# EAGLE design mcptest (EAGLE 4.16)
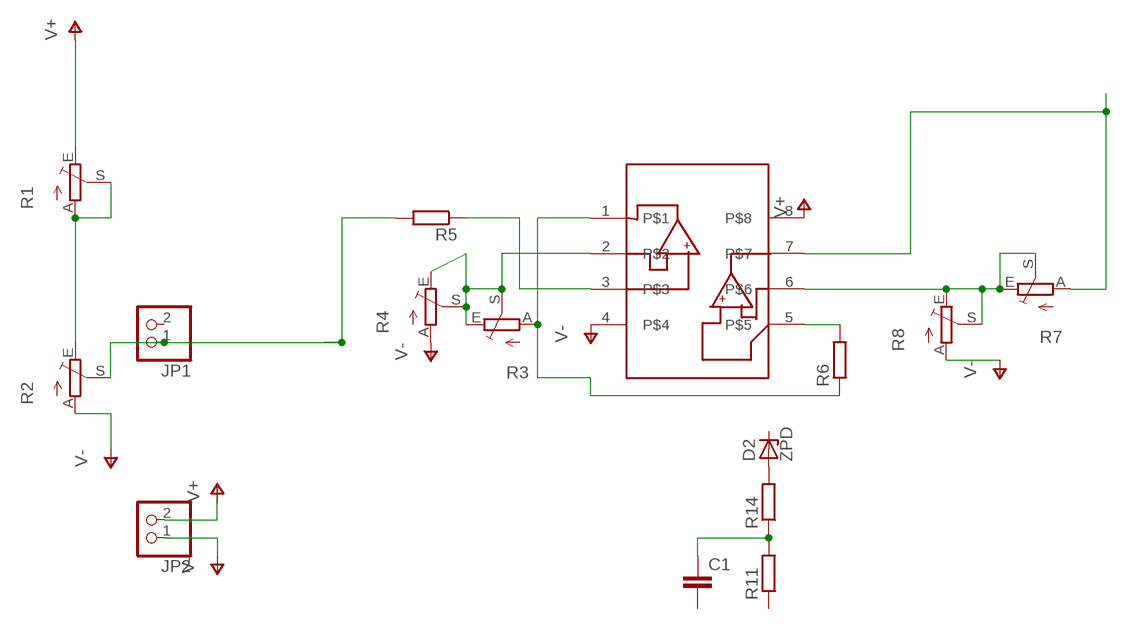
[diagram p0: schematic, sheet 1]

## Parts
C1  C-EU025_050-035X075  [C025_050-035X075]
D2  ZPD  [DO35Z10]
JP1  PINHD-1X2  [1X02]
JP2  PINHD-1X2  [1X02]
R1  TRIM_EU-LI15  [LI15]
R2  TRIM_EU-LI15  [LI15]
R3  TRIM_EU-LI15  [LI15]
R4  TRIM_EU-LI15  [LI15]
R5  R-EU_0207/15  [0207/15]
R6  R-EU_0207/15  [0207/15]
R7  TRIM_EU-LI15  [LI15]
R8  TRIM_EU-LI15  [LI15]
R11  R-EU_0207/10  [0207/10]
R14  R-EU_0207/10  [0207/10]
U$1  MCP6042SOIC  [SO-08]

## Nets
N$1: R7.A U$1.7
N$2: R7.E R7.S R8.E R8.S U$1.6
N$3: R3.E R3.S R4.E R4.S U$1.2
N$4: R3.A R6.1 U$1.1
N$5: R6.2 U$1.5
N$6: R1.A R1.S R2.E
N$7: R5.1 U$1.3
N$8: JP1.1 R2.S R5.2
N$9: C1.1 R11.2 R14.1
N$11: D2.A R14.2
V+: JP2.2 R1.E U$1.8
V-: JP2.1 R2.A R4.A R8.A U$1.4
Unconnected: C1.2 D2.C JP1.2 R11.1

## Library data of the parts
C1 = rcl:C-EU: CAPACITOR, European symbol
D2 = diode:ZPD: Z DIODE
JP1 JP2 = pinhead:PINHD-1X2: PIN HEADER
R1-R4 R7 R8 = pot:TRIM_EU-: POTENTIOMETER
R5 R6 = rcl:R-EU_: RESISTOR, European symbol
R11 R14 = rcl-2:R-EU_: RESISTOR, European symbol
U$1 = microchip-3:MCP6042

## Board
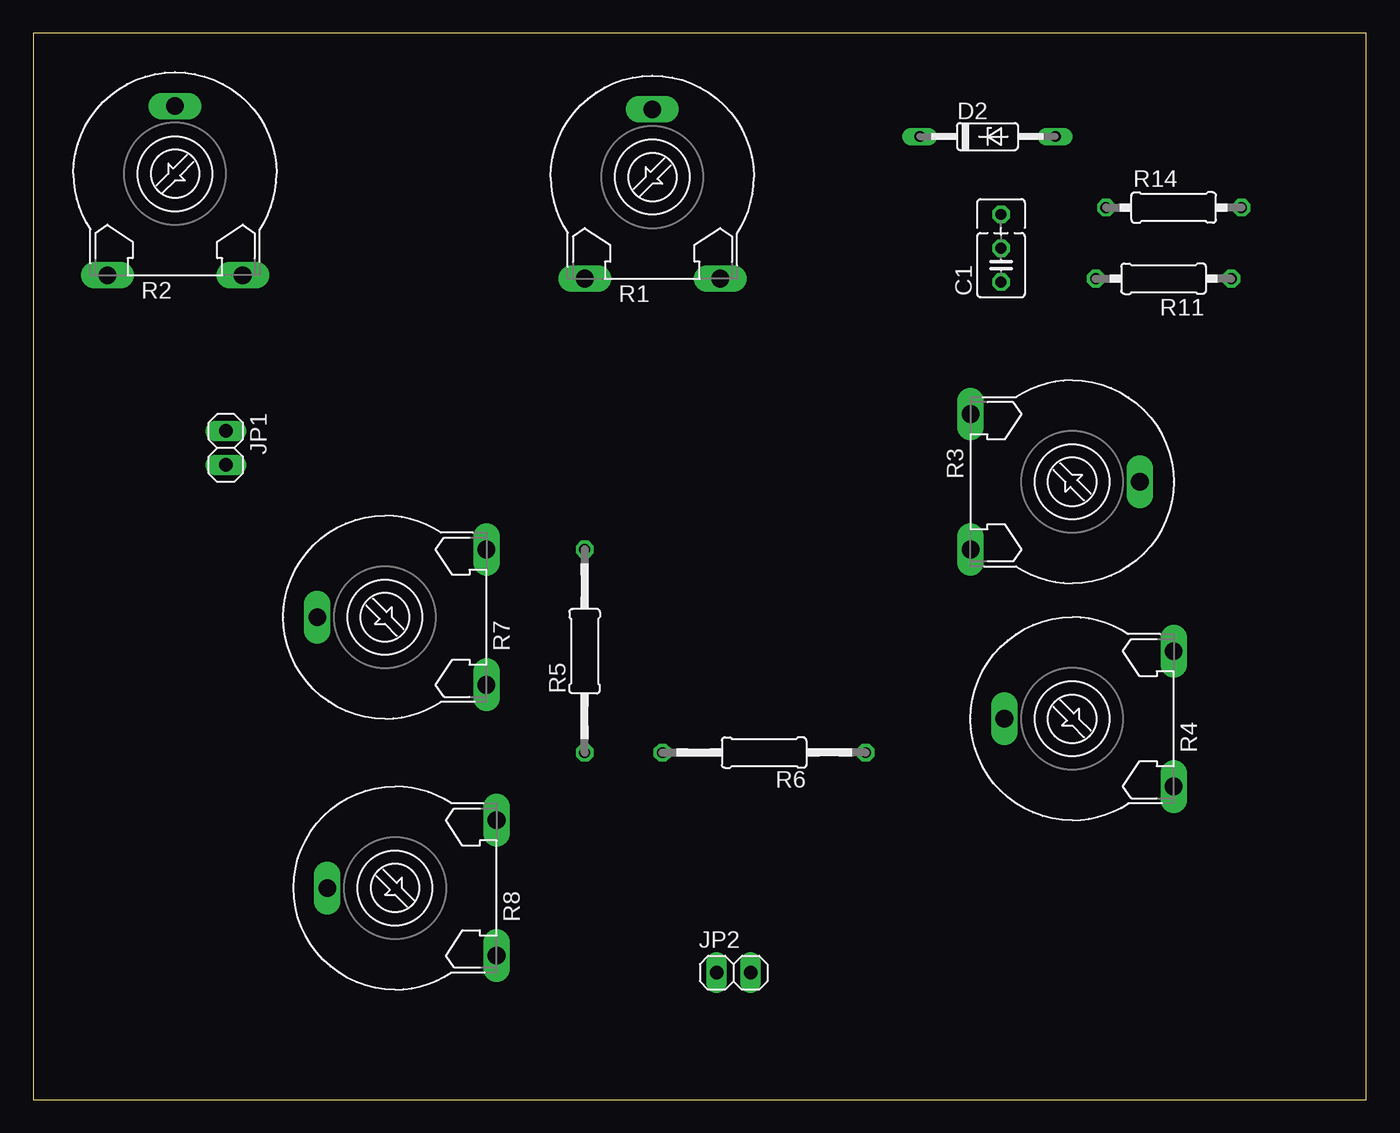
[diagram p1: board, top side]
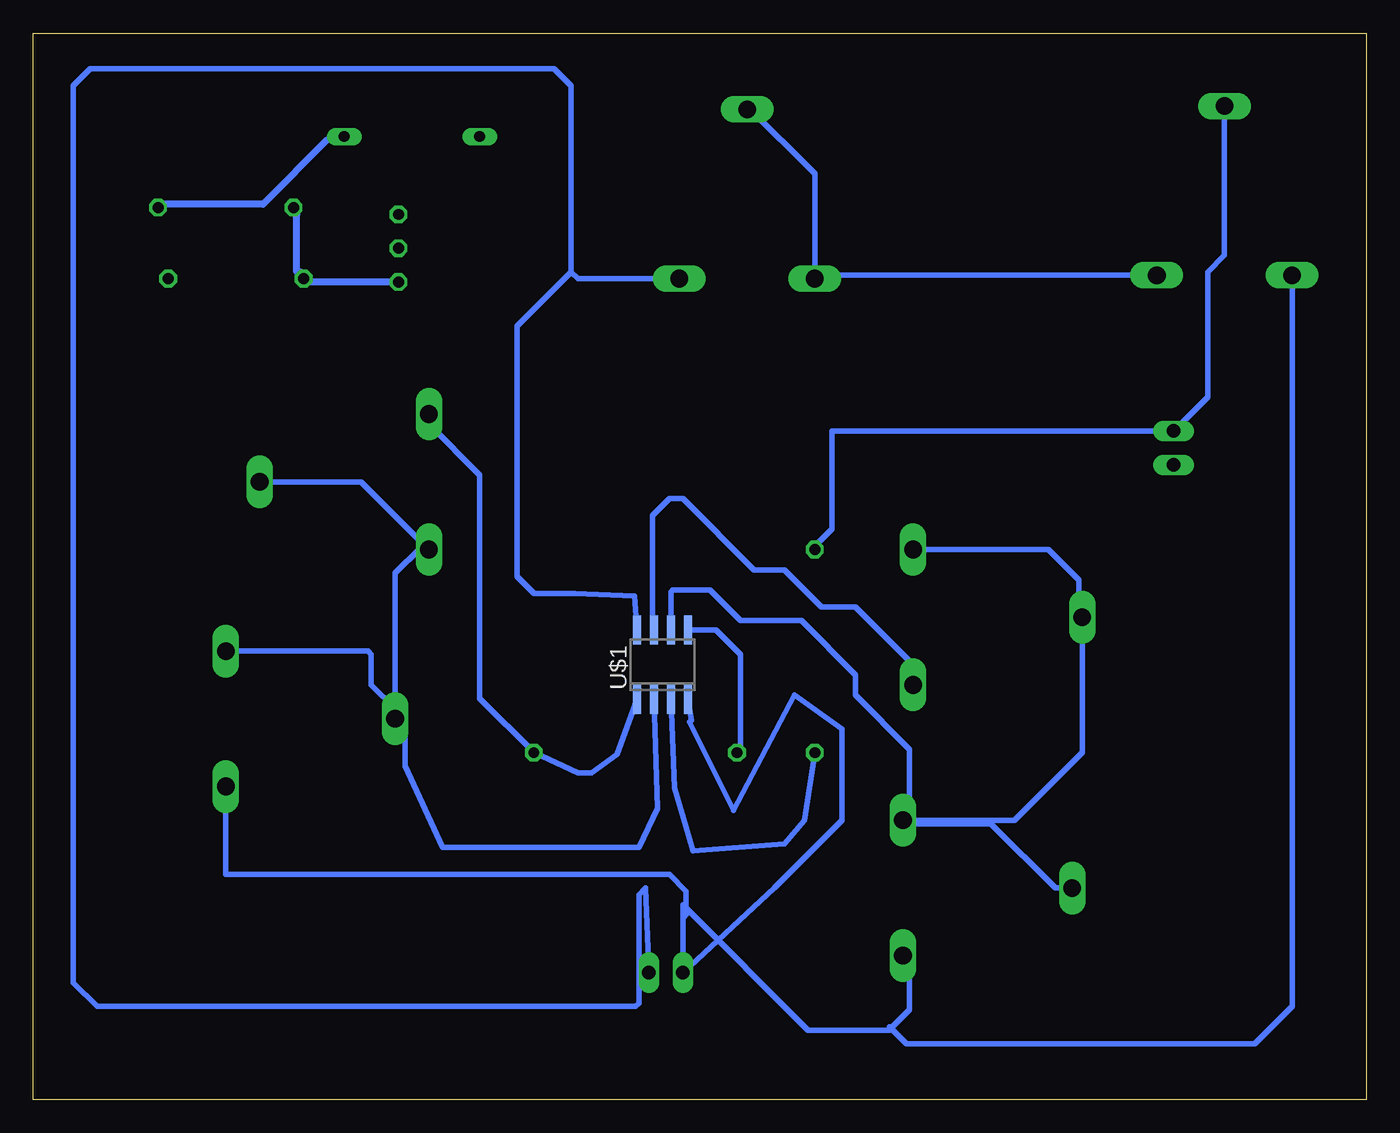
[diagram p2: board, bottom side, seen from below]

Size 100 x 80 mm. Coordinates in mm from the lower left corner, seen from the top.
Outline: 0,0 100,0 100,80 0,80 0,0
Copper layers (1*16): Top 0.035mm / dielectric 1.5mm / Bottom 0.035mm
Design rules "default": minimum track width 20mil, minimum drill 24mil, track to track 20mil, track to pad 20mil, pad to pad 8mil, via to via 8mil, smd to smd 8mil, copper to edge 40mil, drill to drill 8mil, minimum pad ring 10mil, minimum via ring 8mil, stop-mask expansion 4mil, vias tented up to drill 0mil, thermal gap 10mil

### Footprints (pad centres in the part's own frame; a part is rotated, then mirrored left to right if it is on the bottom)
C025_050-035X075 = drill 0.813 octagon: 1 -1.27,0; 2 1.27,0; 3 3.81,0
DO35Z10 = drill 0.813 long: A 5.08,0; C -5.08,0
1X02 = drill 1.016 long: 1 -1.27,0; 2 1.27,0
LI15 = drill 1.321 long: A -5.08,-7.62; E 5.08,-7.62; S 0,5.08
0207/15 = drill 0.813 octagon: 1 -7.62,0; 2 7.62,0
0207/10 = drill 0.813 octagon: 1 -5.08,0; 2 5.08,0
SO-08 = smd 0.6 x 2.2: 1 -1.905,-2.6; 2 -0.635,-2.6; 3 0.635,-2.6; 4 1.905,-2.6; 5 1.905,2.6; 6 0.635,2.6; 7 -0.635,2.6; 8 -1.905,2.6

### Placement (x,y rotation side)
C1  72.61,62.61 90 top
D2  71.59,72.26 0 top
JP1  14.44,48.89 270 top
JP2  52.54,9.52 0 top
R1  46.44,69.21 0 top
R2  10.63,69.46 0 top
R3  77.94,46.35 270 top
R4  77.94,28.57 90 top
R5  41.36,33.65 90 top
R6  54.83,26.03 180 top
R7  26.38,36.19 90 top
R8  27.14,15.87 90 top
R11  84.8,61.59 180 top
R14  85.56,66.92 0 top
U$1  52.79,32.63 0 bottom

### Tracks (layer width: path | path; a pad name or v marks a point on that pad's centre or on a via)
N$1
  Bottom 0.406: R7.A 34,32.63 38.32,36.95 40.86,36.95 43.65,39.75 45.94,39.75 51.27,45.08 52.29,45.08 53.56,43.81 53.56,35.68 53.3,35.43 53.43,35.3 U$1.7
N$2
  Bottom 0.406: R8.S 23.33,15.87 28.16,20.7 35.01,20.7 R8.E | R8.E 26.38,20.95 21.3,26.03 21.3,35.94 | 21.55,36.44 R7.S 21.3,35.94 | R8.E 34.51,21.2 34.51,21.46 34.25,21.71 34.25,26.28 38.32,30.35 38.32,31.87 42.38,35.94 46.95,35.94 49.24,38.22 52.03,38.22 52.16,38.1 52.16,36.06 52.03,35.94 52.03,35.17 52.09,35.23 U$1.6 | R7.E 23.84,41.27 21.55,38.98 21.55,36.19 21.3,35.94
N$3
  Bottom 0.406: U$1.2 53.17,21.84 54.57,18.92 69.3,18.92 72.1,25.01 72.1,28.06 72.86,28.82 R4.S 72.86,29.33 | 72.86,29.33 72.86,39.49 70.95,41.4 70.7,41.65 | 70.7,41.65 70.57,41.78 70.83,41.78 | R4.E 74.89,33.65 74.64,33.4 74.64,31.11 72.86,29.33 | 70.7,41.65 70.57,41.52 | R3.S 75.4,46.35 70.7,41.65
  Bottom 0.508: R3.E 70.83,41.27 70.95,41.4
N$4
  Bottom 0.406: U$1.1 56.22,25.9 58.13,24.51 59.14,24.51 R6.1 66.51,30.09 66.51,46.86 70.32,50.67 R3.A
N$5
  Bottom 0.406: U$1.5 48.79,35.23 46.95,33.4 46.95,26.03 47.21,25.78 R6.2
N$6
  Bottom 0.406: 41.36,62.1 R1.A | R2.E 41.11,61.84 41.36,62.1 | R1.S 46.44,74.54 41.36,69.46 41.36,62.1
N$7
  Bottom 0.406: U$1.3 51.91,23.36 51.02,20.44 50.51,18.66 43.65,19.17 42.13,20.95 R5.1
N$8
  Bottom 0.406: R5.2 41.62,41.27 40.09,42.79 40.09,50.16 JP1.1 11.9,52.7 11.9,62.1 10.63,63.37 R2.S
N$9
  Bottom 0.508: C1.1 79.21,61.34 R11.2 79.97,62.1 80.23,62.1 80.23,66.42 R14.1
N$11
  Bottom 0.508: D2.A 77.94,72 82.77,67.18 90.13,67.18 R14.2
V+
  Bottom 0.406: R1.E 59.14,61.59 59.65,62.1 | 59.65,62.1 59.65,76.07 60.92,77.34 95.72,77.34 96.99,76.07 96.99,8.76 95.21,6.98 54.83,6.98 54.57,7.23 54.57,15.36 54.06,15.87 JP2.2 | U$1.8 54.89,37.77 59.4,37.97 62.45,37.97 63.72,39.24 63.72,58.03 59.65,62.1
V-
  Bottom 0.406: 51.27,13.58 51.27,14.6 41.87,5.2 35.78,5.2 35.65,5.33 | 51.27,13.58 JP2.1 44.41,15.87 39.33,20.95 39.33,27.81 42.89,30.35 47.46,21.71 50.76,28.32 50.63,28.44 U$1.4 | 35.65,5.33 34.25,6.73 34.25,10.54 34.76,11.04 R8.A | R2.A 5.55,6.98 8.34,4.19 34.51,4.19 35.65,5.33 | 35.65,5.33 35.78,5.46 | R4.A 85.56,16.89 52.29,16.89 51.02,15.62 51.02,13.84 51.27,13.58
